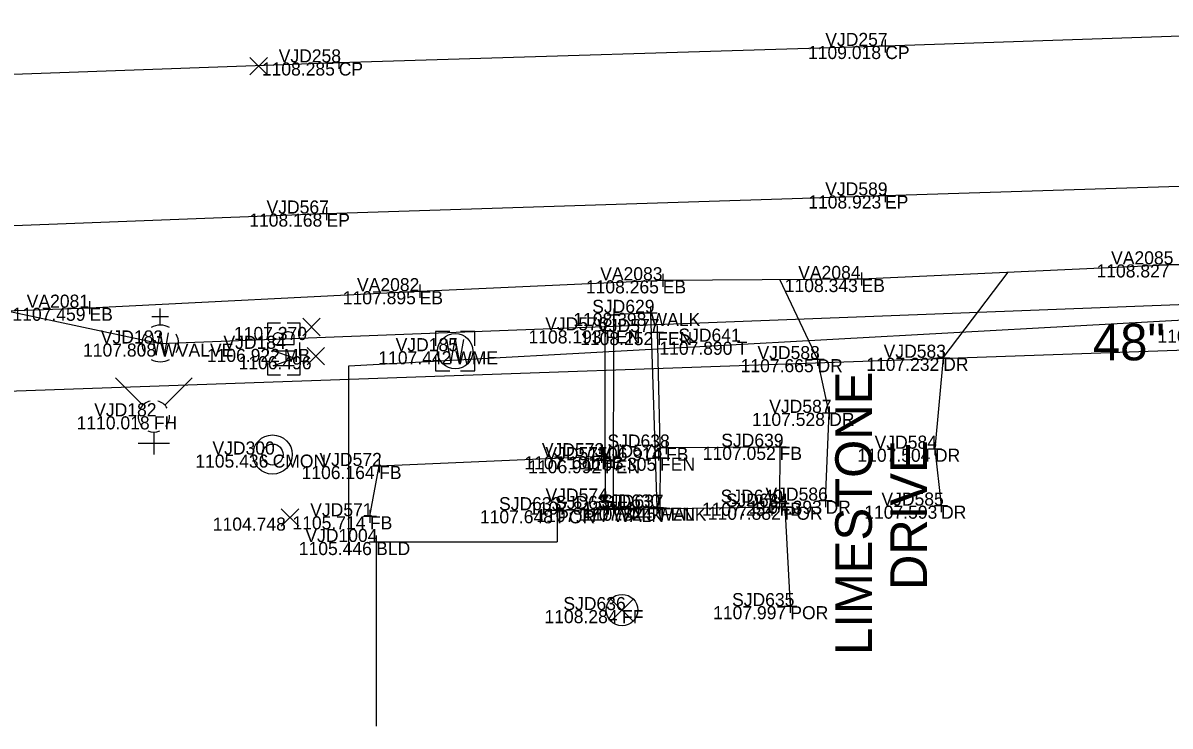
# Model space of a CAD drawing. Extents: x 1629915 to 1630675, y 484401 to 484601.
# Drawn here: x 1630337.7 to 1630425.3, y 484441.7 to 484495.4 of the extents above; entities that cross this region are included whole.
import ezdxf

# ---------------------------------------------------------------- set-up
doc = ezdxf.new("R2010")
doc.units = 0
for name, color, linetype in [('BD_X_Building', 7, 'Continuous'), ('BD_X_Porch_or_Deck', 7, 'Continuous'), ('BR_X_Sub_Foot_Object', 7, 'Continuous'), ('PV_X_COP', 7, 'Continuous'), ('PV_X_Driveway', 7, 'Continuous'), ('PV_X_EOP', 7, 'Continuous'), ('PV_X_Shoulder_Aggregate', 7, 'Continuous'), ('PV_X_Walk', 7, 'Continuous'), ('RD_X_Cells', 7, 'Continuous'), ('RD_X_Fence', 7, 'Continuous'), ('SC_Scratch1', 7, 'Continuous'), ('SV_X_Mon_Cells_Found', 7, 'Continuous'), ('SV_X_Random_Point', 7, 'Continuous'), ('SV_X_Shot_Marker', 7, 'Continuous'), ('SV_X_Text_Comment', 7, 'Continuous'), ('SV_X_Text_Elevation', 7, 'Continuous'), ('SV_X_Text_Name', 7, 'Continuous'), ('TX_X_20', 7, 'Continuous'), ('UT_X_Gas', 7, 'Continuous'), ('UT_X_Water', 7, 'Continuous'), ('UT_X_Water_Cells', 7, 'Continuous'), ('VG_X_Flower_Bed', 7, 'Continuous')]:
    doc.layers.add(name, color=color, linetype=linetype)

msp = doc.modelspace()

# ---------------------------------------------------------------- linework, layer by layer
at = {"layer": 'BD_X_Building'}
for q in [(1630378.519, 484455.762), (1630364.695, 484441.696)]:
    msp.add_line((1630364.695, 484455.762), q, dxfattribs=at)
at = {"layer": 'BD_X_Porch_or_Deck'}
msp.add_line((1630378.519, 484458.187), (1630378.519, 484455.762), dxfattribs=at)
msp.add_lwpolyline([(1630378.519, 484458.187), (1630395.89, 484458.458), (1630396.318, 484450.858)], dxfattribs=at)
at = {"layer": 'BR_X_Sub_Foot_Object'}
msp.add_line((1630334.981, 484467.226), (1630537.673, 484474.324), dxfattribs=at)
at = {"layer": 'PV_X_COP'}
msp.add_lwpolyline([(1630297.366, 484489.973), (1630308.553, 484490.492), (1630361.839, 484492.402), (1630403.565, 484493.662), (1630440.464, 484494.931), (1630486.149, 484496.207), (1630529.234, 484497.459), (1630568.325, 484498.484), (1630611.926, 484499.834), (1630649.713, 484500.97)], dxfattribs=at)
at = {"layer": 'PV_X_Driveway'}
for p, q in [((1630398.393, 484469.732), (1630395.529, 484475.815)), ((1630407.988, 484469.838), (1630412.961, 484476.381))]:
    msp.add_line(p, q, dxfattribs=at)
for points in [[(1630399.007, 484458.919), (1630399.285, 484465.626), (1630398.393, 484469.732)], [(1630407.988, 484469.838), (1630407.357, 484462.889), (1630407.826, 484458.539)]]:
    msp.add_lwpolyline(points, dxfattribs=at)
at = {"layer": 'PV_X_EOP'}
msp.add_lwpolyline([(1630292.708, 484478.565), (1630303.888, 484478.677), (1630360.908, 484480.855), (1630403.548, 484482.238), (1630442.06, 484483.465), (1630486.339, 484484.798), (1630529.418, 484485.732), (1630568.745, 484486.748), (1630610.183, 484487.853), (1630650.035, 484489.089)], dxfattribs=at)
at = {"layer": 'PV_X_Shoulder_Aggregate'}
msp.add_lwpolyline([(1630290.023, 484472.094), (1630316.065, 484472.69), (1630342.812, 484473.661), (1630368.021, 484474.923), (1630386.578, 484475.757), (1630401.756, 484475.856), (1630425.589, 484476.973), (1630451.796, 484477.683), (1630475.368, 484478.476), (1630505.195, 484479.358), (1630508.151, 484481.327), (1630508.061, 484484.385), (1630516.813, 484484.736), (1630516.951, 484481.103), (1630520.694, 484479.601), (1630540.986, 484479.176), (1630540.508, 484484.672), (1630564.841, 484485.646), (1630589.64, 484486.306), (1630613.109, 484486.832)], dxfattribs=at)
at = {"layer": 'PV_X_Walk'}
msp.add_lwpolyline([(1630385.651, 484473.266), (1630386.124, 484458.391), (1630382.815, 484458.285), (1630382.835, 484473.111), (1630382.835, 484473.176)], close=True, dxfattribs=at)
at = {"layer": 'RD_X_Cells'}
for p, q in [((1630356.423, 484470.007), (1630356.423, 484471.008)), ((1630357.644, 484470.518), (1630357.644, 484470.518)), ((1630358.866, 484470.007), (1630358.866, 484471.008))]:
    msp.add_line(p, q, dxfattribs=at)
for points in [[(1630356.423, 484471.525), (1630356.423, 484472.518), (1630357.393, 484472.518)], [(1630357.896, 484472.518), (1630358.866, 484472.518), (1630358.866, 484471.525)], [(1630357.575, 484471.54), (1630357.512, 484471.603), (1630357.474, 484471.641), (1630357.436, 484471.666), (1630357.411, 484471.679), (1630357.361, 484471.704), (1630357.323, 484471.716), (1630357.235, 484471.742), (1630357.197, 484471.742), (1630357.147, 484471.742), (1630357.071, 484471.729), (1630357.008, 484471.704), (1630356.958, 484471.666), (1630356.907, 484471.603), (1630356.882, 484471.553), (1630356.869, 484471.527), (1630356.844, 484471.464), (1630356.844, 484470.847), (1630358.444, 484470.847), (1630358.444, 484471.54), (1630358.394, 484471.628), (1630358.331, 484471.704), (1630358.23, 484471.767), (1630358.117, 484471.805), (1630358.003, 484471.817), (1630357.928, 484471.817), (1630357.852, 484471.792), (1630357.739, 484471.742), (1630357.663, 484471.679), (1630357.575, 484471.54), (1630357.575, 484470.847)], [(1630358.444, 484469.222), (1630356.844, 484469.222), (1630358.444, 484469.801), (1630356.844, 484470.356), (1630358.444, 484470.356)], [(1630357.393, 484468.518), (1630356.423, 484468.518), (1630356.423, 484469.488)], [(1630358.866, 484469.488), (1630358.866, 484468.518), (1630357.896, 484468.518)]]:
    msp.add_lwpolyline(points, dxfattribs=at)
at = {"layer": 'RD_X_Fence'}
for points in [[(1630382.231, 484458.851), (1630382.174, 484462.012), (1630382.194, 484471.931)], [(1630386.147, 484471.801), (1630386.372, 484462.201), (1630386.364, 484458.383)]]:
    msp.add_lwpolyline(points, dxfattribs=at)
at = {"layer": 'SC_Scratch1'}
for p, q in [((1630384.319, 484449.708), (1630382.622, 484451.405)), ((1630382.622, 484449.708), (1630384.319, 484451.405))]:
    msp.add_line(p, q, dxfattribs=at)
msp.add_circle((1630383.471, 484450.557), 1.2, dxfattribs=at)
at = {"layer": 'SV_X_Mon_Cells_Found'}
for radius in [1.5, 0.8]:
    msp.add_circle((1630356.794, 484462.441), radius, dxfattribs=at)
at = {"layer": 'SV_X_Random_Point'}
for p, q in [((1630355.062, 484491.455), (1630356.395, 484492.79)), ((1630355.062, 484492.79), (1630356.395, 484491.455)), ((1630359.089, 484471.524), (1630360.422, 484472.859)), ((1630359.089, 484472.859), (1630360.422, 484471.524)), ((1630359.43, 484469.289), (1630360.763, 484470.624)), ((1630359.43, 484470.624), (1630360.763, 484469.289)), ((1630357.459, 484456.961), (1630358.792, 484458.296)), ((1630357.459, 484458.296), (1630358.792, 484456.961))]:
    msp.add_line(p, q, dxfattribs=at)
at = {"layer": 'SV_X_Shot_Marker'}
for p, q in [((1630403.565, 484494.162), (1630403.565, 484493.162)), ((1630403.065, 484493.662), (1630404.065, 484493.662)), ((1630403.565, 484493.662), (1630403.565, 484493.662)), ((1630361.339, 484492.402), (1630362.339, 484492.402)), ((1630361.839, 484492.902), (1630361.839, 484491.902)), ((1630361.839, 484492.402), (1630361.839, 484492.402)), ((1630403.548, 484482.738), (1630403.548, 484481.738)), ((1630403.048, 484482.238), (1630404.048, 484482.238)), ((1630403.548, 484482.238), (1630403.548, 484482.238)), ((1630360.908, 484481.355), (1630360.908, 484480.355)), ((1630360.408, 484480.855), (1630361.408, 484480.855)), ((1630360.908, 484480.855), (1630360.908, 484480.855)), ((1630425.089, 484476.973), (1630426.089, 484476.973)), ((1630386.078, 484475.757), (1630387.078, 484475.757)), ((1630386.578, 484476.257), (1630386.578, 484475.257)), ((1630386.578, 484475.757), (1630386.578, 484475.757)), ((1630401.256, 484475.856), (1630402.256, 484475.856)), ((1630401.756, 484476.356), (1630401.756, 484475.356)), ((1630401.756, 484475.856), (1630401.756, 484475.856)), ((1630367.521, 484474.923), (1630368.521, 484474.923)), ((1630368.021, 484475.423), (1630368.021, 484474.423)), ((1630368.021, 484474.923), (1630368.021, 484474.923)), ((1630342.812, 484474.161), (1630342.812, 484473.161)), ((1630342.312, 484473.661), (1630343.312, 484473.661)), ((1630342.812, 484473.661), (1630342.812, 484473.661)), ((1630382.335, 484473.111), (1630383.335, 484473.111)), ((1630382.835, 484473.611), (1630382.835, 484472.611)), ((1630382.835, 484473.111), (1630382.835, 484473.111)), ((1630385.151, 484473.266), (1630386.151, 484473.266)), ((1630385.651, 484473.766), (1630385.651, 484472.766)), ((1630385.651, 484473.266), (1630385.651, 484473.266)), ((1630382.194, 484472.431), (1630382.194, 484471.431)), ((1630386.147, 484472.301), (1630386.147, 484471.301)), ((1630381.694, 484471.931), (1630382.694, 484471.931)), ((1630382.194, 484471.931), (1630382.194, 484471.931)), ((1630385.647, 484471.801), (1630386.647, 484471.801)), ((1630386.147, 484471.801), (1630386.147, 484471.801)), ((1630397.893, 484469.732), (1630398.893, 484469.732)), ((1630398.393, 484470.232), (1630398.393, 484469.232)), ((1630398.393, 484469.732), (1630398.393, 484469.732)), ((1630407.488, 484469.838), (1630408.488, 484469.838)), ((1630407.988, 484470.338), (1630407.988, 484469.338)), ((1630407.988, 484469.838), (1630407.988, 484469.838)), ((1630399.285, 484466.126), (1630399.285, 484465.126)), ((1630398.785, 484465.626), (1630399.785, 484465.626)), ((1630399.285, 484465.626), (1630399.285, 484465.626)), ((1630386.831, 484463.475), (1630386.831, 484462.475)), ((1630395.506, 484463.536), (1630395.506, 484462.536)), ((1630407.357, 484463.389), (1630407.357, 484462.389)), ((1630381.894, 484462.816), (1630381.894, 484461.816)), ((1630382.174, 484462.512), (1630382.174, 484461.512)), ((1630386.331, 484462.975), (1630387.331, 484462.975)), ((1630386.372, 484462.701), (1630386.372, 484461.701)), ((1630386.831, 484462.975), (1630386.831, 484462.975)), ((1630395.006, 484463.036), (1630396.006, 484463.036)), ((1630395.506, 484463.036), (1630395.506, 484463.036)), ((1630406.857, 484462.889), (1630407.857, 484462.889)), ((1630407.357, 484462.889), (1630407.357, 484462.889)), ((1630364.926, 484462.07), (1630364.926, 484461.07)), ((1630381.394, 484462.316), (1630382.394, 484462.316)), ((1630381.674, 484462.012), (1630382.674, 484462.012)), ((1630381.894, 484462.316), (1630381.894, 484462.316)), ((1630382.174, 484462.012), (1630382.174, 484462.012)), ((1630385.872, 484462.201), (1630386.872, 484462.201)), ((1630386.372, 484462.201), (1630386.372, 484462.201)), ((1630364.426, 484461.57), (1630365.426, 484461.57)), ((1630364.926, 484461.57), (1630364.926, 484461.57)), ((1630382.231, 484459.351), (1630382.231, 484458.351)), ((1630395.49, 484459.261), (1630395.49, 484458.261)), ((1630399.007, 484459.419), (1630399.007, 484458.419)), ((1630407.826, 484459.039), (1630407.826, 484458.039)), ((1630364.227, 484458.226), (1630364.227, 484457.226)), ((1630378.019, 484458.187), (1630379.019, 484458.187)), ((1630378.519, 484458.687), (1630378.519, 484457.687)), ((1630378.519, 484458.187), (1630378.519, 484458.187)), ((1630381.731, 484458.851), (1630382.731, 484458.851)), ((1630382.231, 484458.851), (1630382.231, 484458.851)), ((1630382.315, 484458.285), (1630383.315, 484458.285)), ((1630382.815, 484458.785), (1630382.815, 484457.785)), ((1630382.815, 484458.285), (1630382.815, 484458.285)), ((1630385.624, 484458.391), (1630386.624, 484458.391)), ((1630385.864, 484458.383), (1630386.864, 484458.383)), ((1630386.124, 484458.891), (1630386.124, 484457.891)), ((1630386.124, 484458.391), (1630386.124, 484458.391)), ((1630386.364, 484458.883), (1630386.364, 484457.883)), ((1630386.364, 484458.383), (1630386.364, 484458.383)), ((1630394.99, 484458.761), (1630395.99, 484458.761)), ((1630395.391, 484458.458), (1630396.391, 484458.458)), ((1630395.49, 484458.761), (1630395.49, 484458.761)), ((1630395.891, 484458.958), (1630395.891, 484457.958)), ((1630395.891, 484458.458), (1630395.891, 484458.458)), ((1630398.507, 484458.919), (1630399.507, 484458.919)), ((1630399.007, 484458.919), (1630399.007, 484458.919)), ((1630407.326, 484458.539), (1630408.326, 484458.539)), ((1630407.826, 484458.539), (1630407.826, 484458.539)), ((1630363.727, 484457.726), (1630364.727, 484457.726)), ((1630364.227, 484457.726), (1630364.227, 484457.726)), ((1630364.195, 484455.762), (1630365.195, 484455.762)), ((1630364.695, 484456.262), (1630364.695, 484455.262)), ((1630364.695, 484455.762), (1630364.695, 484455.762)), ((1630396.318, 484451.358), (1630396.318, 484450.358)), ((1630395.818, 484450.858), (1630396.818, 484450.858)), ((1630396.318, 484450.858), (1630396.318, 484450.858))]:
    msp.add_line(p, q, dxfattribs=at)
at = {"layer": 'UT_X_Gas'}
for p, q in [((1630362.604, 484469.23), (1630437.584, 484473.366)), ((1630362.604, 484454.759), (1630362.604, 484469.23))]:
    msp.add_line(p, q, dxfattribs=at)
at = {"layer": 'UT_X_Water'}
for p, q in [((1630348.219, 484470.927), (1630675.08, 484483.409)), ((1630327.506, 484475.345), (1630348.219, 484470.927))]:
    msp.add_line(p, q, dxfattribs=at)
at = {"layer": 'UT_X_Water_Cells'}
for p, q in [((1630348.219, 484472.327), (1630348.219, 484473.599)), ((1630348.854, 484472.964), (1630347.583, 484472.964)), ((1630348.219, 484470.927), (1630348.219, 484470.927)), ((1630370.736, 484470.337), (1630370.736, 484470.337)), ((1630346.881, 484466.214), (1630344.801, 484468.292)), ((1630348.573, 484466.214), (1630350.653, 484468.292)), ((1630347.726, 484465.365), (1630347.726, 484465.365)), ((1630347.726, 484465.365), (1630347.726, 484465.365)), ((1630347.728, 484464.162), (1630347.728, 484462.442)), ((1630346.528, 484463.302), (1630348.928, 484463.302))]:
    msp.add_line(p, q, dxfattribs=at)
for points in [[(1630347.583, 484471.747), (1630347.901, 484470.024), (1630348.219, 484471.747), (1630348.539, 484470.024), (1630348.856, 484471.747)], [(1630370.336, 484471.837), (1630369.236, 484471.837), (1630369.236, 484470.737)], [(1630372.236, 484470.737), (1630372.236, 484471.837), (1630371.136, 484471.837)], [(1630370.069, 484471.237), (1630370.403, 484469.437), (1630370.736, 484471.237), (1630371.069, 484469.437), (1630371.403, 484471.237)], [(1630369.236, 484469.937), (1630369.236, 484468.837), (1630370.336, 484468.837)], [(1630371.136, 484468.837), (1630372.236, 484468.837), (1630372.236, 484469.937)]]:
    msp.add_lwpolyline(points, dxfattribs=at)
msp.add_circle((1630370.736, 484470.337), 1.35, dxfattribs=at)
for centre, radius, start, end in [((1630348.219, 484470.929), 1.4, 60.01836, 120.01574), ((1630348.219, 484470.929), 1.4, 150.01836, 209.98164), ((1630348.219, 484470.929), 1.4, 330.01836, 29.98164), ((1630348.219, 484470.929), 1.4, 239.98426, 299.98164), ((1630347.726, 484465.365), 1.2, 103.82389, 149.90967), ((1630347.726, 484465.365), 1.2, 31.87877, 75.84793), ((1630347.726, 484465.365), 1.2, 176.01648, 219.98885), ((1630347.726, 484465.365), 1.2, 320.02099, 4.06293), ((1630347.726, 484465.365), 1.2, 248.13946, 292.03798)]:
    msp.add_arc(centre, radius, start, end, dxfattribs=at)
at = {"layer": 'VG_X_Flower_Bed'}
for points in [[(1630386.831, 484462.975), (1630395.506, 484463.036), (1630395.49, 484458.761)], [(1630364.227, 484457.726), (1630364.926, 484461.57), (1630381.894, 484462.316)]]:
    msp.add_lwpolyline(points, dxfattribs=at)

# ---------------------------------------------------------------- texts
at = {"layer": 'SV_X_Text_Comment'}
for s, p in [('CP', (1630403.565, 484492.662)), ('CP', (1630361.839, 484491.402)), ('EP', (1630403.548, 484481.238)), ('EP', (1630360.908, 484479.855)), ('EB', (1630386.578, 484474.757)), ('EB', (1630401.756, 484474.856)), ('EB', (1630368.021, 484473.923)), ('EB', (1630342.812, 484472.661)), ('WALK', (1630385.651, 484472.266)), ('FEN', (1630382.194, 484470.931)), ('FEN', (1630386.147, 484470.801)), ('WVALVE', (1630348.219, 484469.927)), ('MB', (1630357.644, 484469.518)), ('T', (1630392.232, 484470.064)), ('WME', (1630370.736, 484469.337)), ('DR', (1630398.393, 484468.732)), ('DR', (1630407.988, 484468.838)), ('FH', (1630347.726, 484464.365)), ('DR', (1630399.285, 484464.626)), ('FB', (1630386.831, 484461.975)), ('FB', (1630395.506, 484462.036)), ('DR', (1630407.357, 484461.889)), ('CMON', (1630356.794, 484461.441)), ('FB', (1630381.894, 484461.316)), ('FEN', (1630382.174, 484461.012)), ('FEN', (1630386.372, 484461.201)), ('FB', (1630364.926, 484460.57)), ('POR', (1630378.519, 484457.187)), ('FEN', (1630382.231, 484457.851)), ('WALK', (1630382.815, 484457.285)), ('WALK', (1630386.124, 484457.391)), ('FEN', (1630386.364, 484457.383)), ('FB', (1630395.49, 484457.761)), ('POR', (1630395.891, 484457.458)), ('DR', (1630399.007, 484457.919)), ('DR', (1630407.826, 484457.539)), ('FB', (1630364.227, 484456.726)), ('BLD', (1630364.695, 484454.762)), ('FF', (1630383.471, 484449.557)), ('POR', (1630396.318, 484449.858))]:
    msp.add_text(s, height=1, dxfattribs=at).set_placement(p)
at = {"layer": 'SV_X_Text_Elevation'}
for s, p in [('1109.018', (1630397.667, 484492.662)), ('1108.285', (1630355.971, 484491.402)), ('1108.923', (1630397.686, 484481.238)), ('1108.168', (1630355.009, 484479.855)), ('1108.827', (1630419.695, 484475.973)), ('1108.265', (1630380.709, 484474.757)), ('1108.343', (1630395.894, 484474.856)), ('1107.895', (1630362.152, 484473.923)), ('1107.459', (1630336.93, 484472.661)), ('1108.398', (1630379.752, 484472.266)), ('1107.370', (1630353.844, 484471.192)), ('1108.193', (1630376.332, 484470.931)), ('1108.252', (1630380.275, 484470.801)), ('1108.717', (1630424.349, 484470.993)), ('1107.808', (1630342.321, 484469.927)), ('1106.922', (1630351.773, 484469.518)), ('1107.890', (1630386.321, 484470.064)), ('1106.496', (1630354.194, 484468.956)), ('1107.442', (1630364.865, 484469.337)), ('1107.665', (1630392.525, 484468.732)), ('1107.232', (1630402.117, 484468.838)), ('1110.018', (1630341.828, 484464.365)), ('1107.528', (1630393.387, 484464.626)), ('1106.914', (1630380.911, 484461.975)), ('1107.052', (1630389.634, 484462.036)), ('1107.504', (1630401.437, 484461.889)), ('1105.436', (1630350.892, 484461.441)), ('1107.191', (1630376.014, 484461.316)), ('1106.992', (1630376.302, 484461.012)), ('1107.305', (1630380.503, 484461.201)), ('1106.164', (1630359.006, 484460.57)), ('1107.648', (1630372.62, 484457.187)), ('1107.813', (1630376.369, 484457.851)), ('1107.777', (1630376.922, 484457.285)), ('1107.824', (1630380.204, 484457.391)), ('1107.445', (1630380.496, 484457.383)), ('1107.254', (1630389.57, 484457.761)), ('1107.882', (1630390.019, 484457.458)), ('1107.393', (1630393.145, 484457.919)), ('1107.593', (1630401.964, 484457.539)), ('1104.748', (1630352.227, 484456.629)), ('1105.714', (1630358.307, 484456.726)), ('1105.446', (1630358.792, 484454.762)), ('1108.284', (1630377.55, 484449.557)), ('1107.997', (1630390.424, 484449.858))]:
    msp.add_text(s, height=1, dxfattribs=at).set_placement(p)
at = {"layer": 'SV_X_Text_Name'}
for s, p in [('VJD257', (1630398.99, 484493.662)), ('VJD258', (1630357.259, 484492.402)), ('VJD589', (1630398.985, 484482.238)), ('VJD567', (1630356.332, 484480.855)), ('VA2085', (1630420.808, 484476.973)), ('VA2083', (1630381.803, 484475.757)), ('VA2084', (1630396.923, 484475.856)), ('VA2082', (1630363.237, 484474.923)), ('VA2081', (1630338.02, 484473.661)), ('SJD629', (1630381.193, 484473.266)), ('VJD576', (1630377.61, 484471.931)), ('VJD577', (1630381.571, 484471.801)), ('VJD183', (1630343.676, 484470.927)), ('VJD184', (1630353.042, 484470.518)), ('VJD185', (1630366.186, 484470.337)), ('SJD641', (1630387.776, 484471.064)), ('VJD588', (1630393.813, 484469.732)), ('VJD583', (1630403.445, 484469.838)), ('VJD182', (1630343.173, 484465.365)), ('VJD587', (1630394.71, 484465.626)), ('VJD300', (1630352.201, 484462.441)), ('SJD638', (1630382.356, 484462.975)), ('SJD639', (1630391.047, 484463.036)), ('VJD584', (1630402.755, 484462.889)), ('VJD572', (1630360.373, 484461.57)), ('VJD573', (1630377.35, 484462.316)), ('VJD575', (1630377.623, 484462.012)), ('VJD578', (1630381.791, 484462.201)), ('VJD586', (1630394.423, 484458.919)), ('SJD633', (1630374.08, 484458.187)), ('VJD574', (1630377.629, 484458.851)), ('SJD631', (1630378.359, 484458.285)), ('SJD630', (1630381.636, 484458.391)), ('SJD637', (1630381.894, 484458.383)), ('SJD640', (1630391.001, 484458.761)), ('SJD634', (1630391.394, 484458.458)), ('VJD585', (1630403.276, 484458.539)), ('VJD571', (1630359.665, 484457.726)), ('VJD1004', (1630359.295, 484455.762)), ('SJD636', (1630378.992, 484450.557)), ('SJD635', (1630391.873, 484450.858))]:
    msp.add_text(s, height=1, dxfattribs=at).set_placement(p)
at = {"layer": 'TX_X_20'}
msp.add_text('48"', height=2.8, dxfattribs=at).set_placement((1630419.421, 484469.642))
for s, p in [('LIMESTONE', (1630402.551, 484447.136)), ('DRIVE', (1630406.751, 484452.087))]:
    msp.add_text(s, height=2.8, rotation=90, dxfattribs=at).set_placement(p)

doc.saveas('drawing.dxf')
